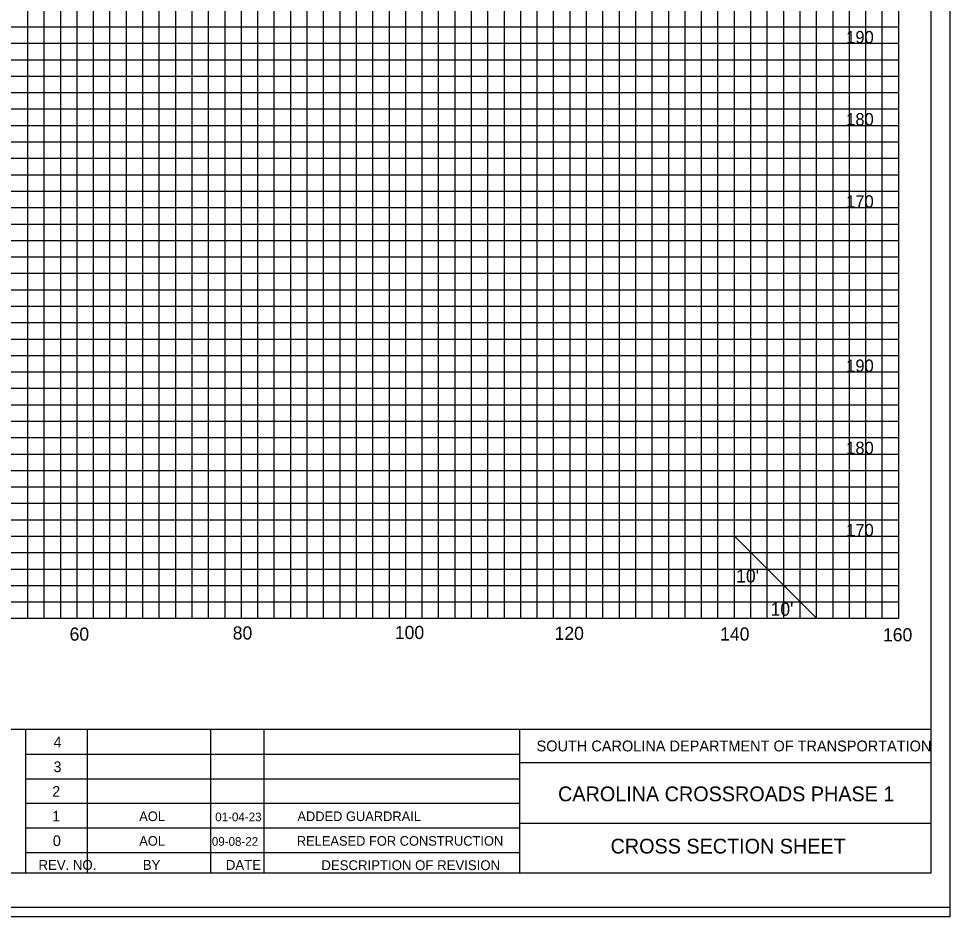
# Model space of a CAD drawing. Extents: x 967 to 1623, y 964 to 7064.
# Drawn here: x 1212.9 to 1326.3, y 6563.7 to 6673 of the extents above; entities that cross this region are included whole.
import ezdxf

# ---------------------------------------------------------------- set-up
doc = ezdxf.new("R2010")
doc.units = 0
for name, color, linetype in [('Default', 7, 'Continuous'), ('RD_SHT_Bndy', 7, 'Continuous'), ('RD_SHT_IplotShp', 7, 'Continuous'), ('RD_SHT_Misc1', 7, 'Continuous'), ('RD_SHT_MjGrid', 7, 'Continuous'), ('RD_SHT_MnGrid', 7, 'Continuous'), ('RD_SHT_TX', 7, 'Continuous'), ('RD_Sketch1', 7, 'Continuous')]:
    doc.layers.add(name, color=color, linetype=linetype)

msp = doc.modelspace()

# ---------------------------------------------------------------- linework, layer by layer
at = {"layer": 'RD_SHT_Bndy'}
for p, q in [((1323.89, 6778.46), (1323.89, 6568.98)), ((996.11, 6586.49), (1323.89, 6586.49)), ((1213.76, 6568.94), (1213.76, 6586.49)), ((1273.88, 6568.98), (1273.88, 6586.49)), ((1221.26, 6568.95), (1221.26, 6586.48)), ((1236.26, 6568.95), (1236.26, 6586.48)), ((1242.76, 6568.95), (1242.76, 6586.48)), ((1213.76, 6583.48), (1273.88, 6583.48)), ((1323.93, 6582.43), (1273.88, 6582.43)), ((1213.76, 6580.48), (1273.88, 6580.48)), ((1213.76, 6577.48), (1273.88, 6577.48)), ((1213.76, 6574.48), (1273.88, 6574.48)), ((1323.89, 6575.04), (1273.88, 6575.04)), ((1213.76, 6571.48), (1273.88, 6571.48)), ((1323.89, 6568.98), (996.11, 6568.98))]:
    msp.add_line(p, q, dxfattribs=at)
at = {"layer": 'RD_SHT_IplotShp'}
for points in [[(967.41, 6563.72), (1326.28, 6563.72), (1326.28, 6783.72), (967.41, 6783.72)], [(988.52, 6564.84), (1326.28, 6564.84), (1326.28, 6782.6), (988.52, 6782.6)]]:
    msp.add_lwpolyline(points, close=True, dxfattribs=at)
at = {"layer": 'RD_SHT_MjGrid'}
for p, q in [((1220, 6600), (1220, 6770)), ((1230, 6600), (1230, 6770)), ((1240, 6600), (1240, 6770)), ((1250, 6600), (1250, 6770)), ((1260, 6600), (1260, 6770)), ((1270, 6600), (1270, 6770)), ((1280, 6600), (1280, 6770)), ((1290, 6600), (1290, 6770)), ((1300, 6600), (1300, 6770)), ((1310, 6600), (1310, 6770)), ((1320, 6600), (1320, 6770)), ((1000, 6670), (1320, 6670)), ((1000, 6660), (1320, 6660)), ((1000, 6650), (1320, 6650)), ((1000, 6640), (1320, 6640)), ((1000, 6630), (1320, 6630)), ((1000, 6620), (1320, 6620)), ((1000, 6610), (1320, 6610)), ((1000, 6600), (1320, 6600))]:
    msp.add_line(p, q, dxfattribs=at)
at = {"layer": 'RD_SHT_MnGrid'}
for p, q in [((1214, 6600), (1214, 6770)), ((1216, 6600), (1216, 6770)), ((1218, 6600), (1218, 6770)), ((1222, 6600), (1222, 6770)), ((1224, 6600), (1224, 6770)), ((1226, 6600), (1226, 6770)), ((1228, 6600), (1228, 6770)), ((1232, 6600), (1232, 6770)), ((1234, 6600), (1234, 6770)), ((1236, 6600), (1236, 6770)), ((1238, 6600), (1238, 6770)), ((1242, 6600), (1242, 6770)), ((1244, 6600), (1244, 6770)), ((1246, 6600), (1246, 6770)), ((1248, 6600), (1248, 6770)), ((1252, 6600), (1252, 6770)), ((1254, 6600), (1254, 6770)), ((1256, 6600), (1256, 6770)), ((1258, 6600), (1258, 6770)), ((1262, 6600), (1262, 6770)), ((1264, 6600), (1264, 6770)), ((1266, 6600), (1266, 6770)), ((1268, 6600), (1268, 6770)), ((1272, 6600), (1272, 6770)), ((1274, 6600), (1274, 6770)), ((1276, 6600), (1276, 6770)), ((1278, 6600), (1278, 6770)), ((1282, 6600), (1282, 6770)), ((1284, 6600), (1284, 6770)), ((1286, 6600), (1286, 6770)), ((1288, 6600), (1288, 6770)), ((1292, 6600), (1292, 6770)), ((1294, 6600), (1294, 6770)), ((1296, 6600), (1296, 6770)), ((1298, 6600), (1298, 6770)), ((1302, 6600), (1302, 6770)), ((1304, 6600), (1304, 6770)), ((1306, 6600), (1306, 6770)), ((1308, 6600), (1308, 6770)), ((1312, 6600), (1312, 6770)), ((1314, 6600), (1314, 6770)), ((1316, 6600), (1316, 6770)), ((1318, 6600), (1318, 6770)), ((1000, 6672), (1320, 6672)), ((1000, 6668), (1320, 6668)), ((1000, 6666), (1320, 6666)), ((1000, 6664), (1320, 6664)), ((1000, 6662), (1320, 6662)), ((1000, 6658), (1320, 6658)), ((1000, 6656), (1320, 6656)), ((1000, 6654), (1320, 6654)), ((1000, 6652), (1320, 6652)), ((1000, 6648), (1320, 6648)), ((1000, 6646), (1320, 6646)), ((1000, 6644), (1320, 6644)), ((1000, 6642), (1320, 6642)), ((1000, 6638), (1320, 6638)), ((1000, 6636), (1320, 6636)), ((1000, 6634), (1320, 6634)), ((1000, 6632), (1320, 6632)), ((1000, 6628), (1320, 6628)), ((1000, 6626), (1320, 6626)), ((1000, 6624), (1320, 6624)), ((1000, 6622), (1320, 6622)), ((1000, 6618), (1320, 6618)), ((1000, 6616), (1320, 6616)), ((1000, 6614), (1320, 6614)), ((1000, 6612), (1320, 6612)), ((1000, 6608), (1320, 6608)), ((1000, 6606), (1320, 6606)), ((1000, 6604), (1320, 6604)), ((1000, 6602), (1320, 6602))]:
    msp.add_line(p, q, dxfattribs=at)
at = {"layer": 'RD_SHT_TX'}
msp.add_line((1300, 6610), (1310, 6600), dxfattribs=at)
at = {"layer": 'RD_Sketch1'}
msp.add_lwpolyline([(967.41, 6563.72), (1326.28, 6563.72), (1326.28, 6783.72), (967.41, 6783.72)], close=True, dxfattribs=at)

# ---------------------------------------------------------------- texts
at = {"layer": 'Default'}
for s, p in [('190', (1313.61, 6670)), ('180', (1313.61, 6660)), ('170', (1313.61, 6650)), ('190', (1313.61, 6630)), ('180', (1313.61, 6620)), ('170', (1313.61, 6610))]:
    msp.add_text(s, height=1.5, dxfattribs=at).set_placement(p)
at = {"layer": 'RD_SHT_Misc1'}
for s, height, p in [('AOL', 1.17, (1227.56, 6575.32)), ('01-04-23', 1.053, (1236.81, 6575.3)), ('ADDED GUARDRAIL', 1.17, (1246.81, 6575.32)), ('AOL', 1.17, (1227.56, 6572.32)), ('09-08-22', 1.053, (1236.4, 6572.31)), ('RELEASED FOR CONSTRUCTION', 1.17, (1246.74, 6572.32))]:
    msp.add_text(s, height=height, dxfattribs=at).set_placement(p)
at = {"layer": 'RD_SHT_TX'}
for s, height, p in [("10'", 1.6, (1300.21, 6604.36)), ("10'", 1.6, (1304.4, 6600.32)), ('80', 1.6, (1238.94, 6597.42)), ('100', 1.6, (1258.67, 6597.48)), ('120', 1.6, (1278.11, 6597.38)), ('60', 1.6, (1219.08, 6597.28)), ('140', 1.6, (1298.26, 6597.29)), ('160', 1.6, (1318.08, 6597.2)), ('4', 1.3, (1217.13, 6584.28)), ('SOUTH CAROLINA DEPARTMENT OF TRANSPORTATION', 1.32, (1275.92, 6583.8)), ('3', 1.3, (1217.13, 6581.28)), ('2', 1.3, (1216.97, 6578.28)), ('1', 1.3, (1216.97, 6575.28)), ('0', 1.3, (1217.05, 6572.28)), ('REV. NO.', 1.2, (1215.3, 6569.38)), ('BY', 1.2, (1227.99, 6569.38)), ('DATE', 1.2, (1238.1, 6569.38)), ('DESCRIPTION OF REVISION', 1.2, (1249.73, 6569.35))]:
    msp.add_text(s, height=height, dxfattribs=at).set_placement(p)
for s, p in [('CAROLINA CROSSROADS PHASE 1', (1278.54, 6577.73)), ('CROSS SECTION SHEET', (1284.93, 6571.37))]:
    msp.add_text(s, height=1.8, rotation=0, dxfattribs=at).set_placement(p)

doc.saveas('drawing.dxf')
